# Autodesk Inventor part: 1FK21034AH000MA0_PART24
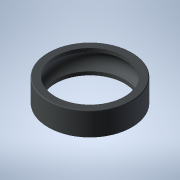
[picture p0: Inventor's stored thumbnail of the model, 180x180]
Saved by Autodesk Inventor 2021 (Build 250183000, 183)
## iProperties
Created: 2025-04
Part Number: 1FK21034AH000MA0_PART24
Material: Generic
Catalog Web Link: www.3dfindit.com
Description: -Servo synchronous motor
Document SubType Name: Modeling
Designer: psAdmin
Mass: 1.46378 g
Surface Area: 23.3636 cm^2
Volume: 1.46378 cm^3
Density: 1 g/cm^3
Appearance: PSOLRGB-212-217-219
Category: PARTsolutions
Title: 1FK21034AH000MA0_PART24
Author: Cadenas PARTsolutions
Comments: Servo synchronous motor
Sending System: PARTsolutions
Preprocessor: ST-DEVELOPER v19.3
PSOL_IDENT_0: {$CADENAS_DATA/23d-libs/siemens_ag/_cat_/ec/b7/1fk21034ah000ma0.prj},216 {VTYP=3D},{NB=1FK21034AH000
PSOL_IDENT_1: MA0_PART24},{LINA=1FK21034AH000MA0_PART24},{NN=1FK21034AH000MA0_PART24},{NOPRJ=TRUE},{DATE=19.08.202
PSOL_IDENT_2: 5 14:01:05},{GEOMDATE=30.07.2025 02:01:02},{VERSION=},{LINEID=10},{WBVAR=},{WBNUMERIC=}  {NB=1FK2103
PSOL_IDENT_3: 4AH000MA0_PART24},{LINA=1FK21034AH000MA0_PART24},{KT=DUMMY},{PREVIEW=../../../_pool_/7c/50/p_d211_xx
PSOL_IDENT_4: _00932j.png},{DESCSHORT=SIMOTICS S-1FK2 HD, SINAMICS S210 3AC 400V-480V, 1.01 Nm, 4500 rpm},{DESCLON
PSOL_IDENT_5: G=SIMOTICS S-1FK2 HD servo motor M0=1.27 Nm; PN = 0.48 kW at nN=4500 rpm (380-480 V); PN = 0.3 kW at
PSOL_IDENT_6: nN=2500 rpm (200-240 V); degree of protection IP64; cylindrical shaft D14 x 30 mm; absolute encoder
PSOL_IDENT_7: 22-bit + 12-bit multiturn (encoder AM22DQC); with OCC interface; plug size M17, rotatable; SIMOTICS
PSOL_IDENT_8: S-1FK2 servomotorfor a wide range of uses in industrial environments. SIMOTICS S‑1FK2 servomotors a
PSOL_IDENT_9: re compact synchronous motors with a high dynamic performance that set themselves apart as a result
PSOL_IDENT_10: of their high power density, degree of protection and overload capability. The motors are available
PSOL_IDENT_11: in two variants: as High Dynamic variant (highest dynamic performance as a result of the low intrins
PSOL_IDENT_12: ic moment of inertia for applications demanding a high dynamic performance with low moved masses) -
PSOL_IDENT_13: and as Compact variant (precise and stable closed-loop control for medium up to large moved masses a
PSOL_IDENT_14: s a result of a medium intrinsic moment of inertia). SIMOTICSS‑1FK2 servomotors fully exploit their
PSOL_IDENT_15: strengths in a system with the SINAMICSS210 frequency converter and simple connection using the one
PSOL_IDENT_16: cable connection (OCC). Advantages include the short control and positioning times, fast and precise
PSOL_IDENT_17: correction of disturbing quantities as well as stable control with a high dynamic performance. The
PSOL_IDENT_18: servo motors can be configured to address a wide range of requirements. For example with and without
PSOL_IDENT_19: holding brake, IP64 or IP65 degree of protection, singleturn or multiturn absolute encoders - to na
PSOL_IDENT_20: me just a few. Further, the servomotors are available in different shaft heights extending from 20 t
PSOL_IDENT_21: o 100. A shaft sealing ring is available to achieve an IP65 degree of protection and for subsequent
PSOL_IDENT_22: mounting at the motor or as spare part. SIMOTICS - the optimum motor for each and every motion contr
PSOL_IDENT_23: ol application.},{INTNO=4034106444822},{SUPPLIERALTNO=1FK2103-4AH00-0MA0},{MANUID=1FK21034AH000MA0},
PSOL_IDENT_24: {MANUNAME=Siemens},{MANUTYPEDESC=SYNCHRONOUS MOTOR 1FK2 HD 1,27 NM},{AAU732=SIMOTICS},{AAO057=S-1FK2
PSOL_IDENT_25: },{AAU734=SIMOTICS S-1FK2 HD servo motor M0=1.27 Nm; PN = 0.48 kW at nN=4500 rpm (380-480 V); PN = 0
PSOL_IDENT_26: .3 kW at nN=2500 rpm (200-240 V); degree of protection IP64; cylindrical shaft D14 x 30 mm; absolute
PSOL_IDENT_27: encoder 22-bit + 12-bit multiturn (encoder AM22DQC); with OCC interface; plug size M17, rotatable;}
PSOL_IDENT_28: ,{AAW338=SYNCHRONOUS MOTOR 1FK2 HD 1,27 NM},{AAO742=SIMOTICS},{AAO663=4034106444822},{NOCUPEROU=1},{
PSOL_IDENT_29: PRICEQUANTITY=1},{QUANTITYMIN=1},{QUANTITYINT=1},{CTN=85015100},{COO=RO},{AAO676=1FK2103-4AH00-0MA0}
PSOL_IDENT_30: ,{AAO677=Siemens AG},{ORDERUNIT=C62},{CONTENTUNIT=C62}
NB: 1FK21034AH000MA0_PART24
NT: Servo synchronous motor
NBSYN: $MANUID._PART24
LINA: 1FK21034AH000MA0_PART24
CATALOG: SIEMENS
PREVIEW: ../../../_pool_/7c/50/p_d211_xx_00932j.png
DESCSHORT: SIMOTICS S-1FK2 HD, SINAMICS S210 3AC 400V-480V, 1.01 Nm, 4500 rpm
DESCLONG: SIMOTICS S-1FK2 HD servo motor M0=1.27 Nm; PN = 0.48 kW at nN=4500 rpm (380-480 V); PN = 0.3 kW at nN=2500 rpm (200-240 V); degree of protection IP64; cylindric
INTNO: 4034106444822
SUPPLIERALTNO: 1FK2103-4AH00-0MA0
MANUID: 1FK21034AH000MA0
MANUNAME: Siemens
MANUTYPEDESC: SYNCHRONOUS MOTOR 1FK2 HD 1,27 NM
AAU732: SIMOTICS
AAO057: S-1FK2
AAU734: SIMOTICS S-1FK2 HD servo motor M0=1.27 Nm; PN = 0.48 kW at nN=4500 rpm (380-480 V); PN = 0.3 kW at nN=2500 rpm (200-240 V); degree of protection IP64; cylindric
AAW338: SYNCHRONOUS MOTOR 1FK2 HD 1,27 NM
AAO742: SIMOTICS
AAO663: 4034106444822.0
NOCUPEROU: 1
PRICEQUANTITY: 1
QUANTITYMIN: 1
QUANTITYINT: 1
CTN: 85015100
COO: RO
ARTICLENO: 1FK21034AH000MA0_PART24
BOMINFO: 1FK21034AH000MA0_PART24
CREATOR: CADENAS GmbH
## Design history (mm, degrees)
feature "2025_04_17_15_01_37_0314"
body "Solid1"
